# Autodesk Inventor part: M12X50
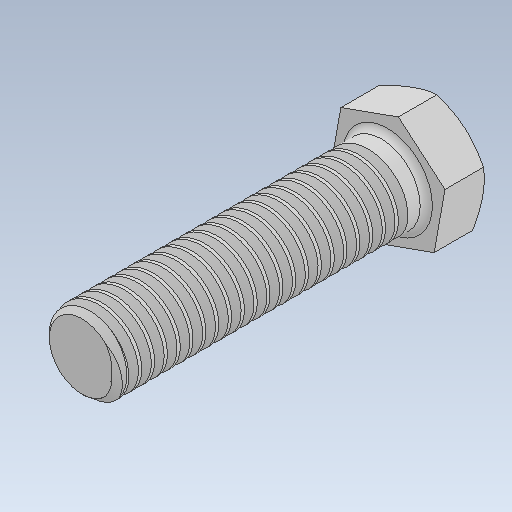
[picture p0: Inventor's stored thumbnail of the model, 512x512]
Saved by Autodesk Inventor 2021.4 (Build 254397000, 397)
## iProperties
Created: 2017-11
Part Number: M12X50
Material: Ogólny
Document SubType Name: Modeling
Designer: user
Density: 1 g/cm^3
Appearance: Domyślna
Author: user
Revision Number: ÈÎºÎ
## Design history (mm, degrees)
feature "ÇÐ³ý-É¨Ãè3"
node "Bryła1"
